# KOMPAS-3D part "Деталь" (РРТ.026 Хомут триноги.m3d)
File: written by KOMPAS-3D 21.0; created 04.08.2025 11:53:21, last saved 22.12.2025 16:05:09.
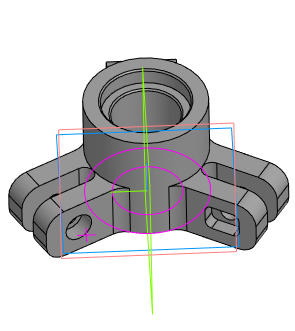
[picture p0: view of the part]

Document properties: Автор: User; Полное имя файла: C:\Users\User\Desktop\Ручной ротатор КД\Модели КД\РРТ.026 Хомут триноги.m3d

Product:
- Part/product: Деталь
    Масса: 0.295818
    Форматы листов документа: A4@4~2
  - Body: Тело 1
      Масса: 0.296152

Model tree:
1. Эскиз:1
2. Элемент выдавливания:1
     Расстояние 1 = 35
3. Эскиз:5  (with: Элемент выдавливания:1)
4. Элемент выдавливания:5
     Расстояние 1 = 17
5. Эскиз:6  (with: Элемент выдавливания:1)
6. Элемент выдавливания:6
     Расстояние 1 = 20
7. Эскиз:7  (with: Элемент выдавливания:5)
8. Отверстие:3  (with: Элемент выдавливания:5)
     Глубина выреза = 34; Диаметр отверстия = 5.2; Угол конуса дна = 118; Расстояние 1 = 14.4334; Расстояние 2 = -8.5; Диаметр цековки = 8.7; Глубина цековки = 5
9. Фаска:1  (with: Отверстие:3)
     Угол = 45; Длина 1 = 0.5; Длина 2 = 0.5
10. Скругление:3  (with: Элемент выдавливания:5)
     Радиус = 6
11. Элемент выдавливания:8  (with: Элемент выдавливания:1)
     Толщина стенки 1 = 2.9; Расстояние 2 = 5
12. Элемент выдавливания:9  (with: Элемент выдавливания:6, Элемент выдавливания:1)
     Расстояние 2 = 36
13. Эскиз:8  (with: Элемент выдавливания:5, Отверстие:3)
14. Элемент выдавливания:10
     Расстояние 2 = 8
15. Массив по концентрической сетке:5  (with: Элемент выдавливания:10, Эскиз:8, Эскиз:7, Отверстие:3, Элемент выдавливания:1)  (3 pattern instances)
     Шаг 2 = 360
16. Элемент выдавливания:12  (with: Элемент выдавливания:8)
     Расстояние 2 = 44
17. Скругление:4  (with: Элемент выдавливания:9, Элемент выдавливания:6)
     Радиус = 3
18. Фаска:2  (with: Элемент выдавливания:8)
     Угол = 45; Длина 1 = 0.5; Длина 2 = 0.5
